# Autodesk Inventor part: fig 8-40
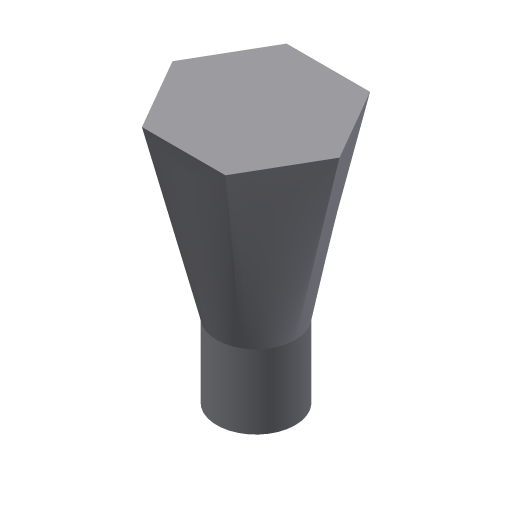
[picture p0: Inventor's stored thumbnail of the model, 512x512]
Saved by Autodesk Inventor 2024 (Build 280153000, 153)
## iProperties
Created: 2004-05
Part Number: fig 8-40
Document SubType Name: Modeling
Designer: CADCIM Technologies
Manufacturer: Standard
Standards Organization: Custom
Density: 1 g/cm^3
Material: Generic
Appearance: Default
Author: CADCIM Technologies
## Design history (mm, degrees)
sketch "Sketch1"
  geometry: C1 r 16.344 at (0, 0)
  constraints: 1 centre point
extrude "Extrusion1" new body sketch "Sketch1" distance "d0" = 30.75; taper "d1" = 0 deg
workplane "Work Plane1"
sketch "Sketch2"
  geometry: L1 (34.788, 0)-(17.394, -30.128); L2 (17.394, -30.128)-(-17.394, -30.128); L3 (-17.394, -30.128)-(-34.788, 0); L4 (-34.788, 0)-(-17.394, 30.128); L5 (-17.394, 30.128)-(17.394, 30.128); L6 (17.394, 30.128)-(34.788, 0); 2 further points
  constraints: 12 end point, 1 coincident, 12 other
loft "Loft2" sketch "Sketch2" dims "d7" = 0, "d8" = 90 deg, "d9" = 0, "d10" = 90 deg
  node "Edges2"
body "Solid1"
other parameters: "d2" = 75
